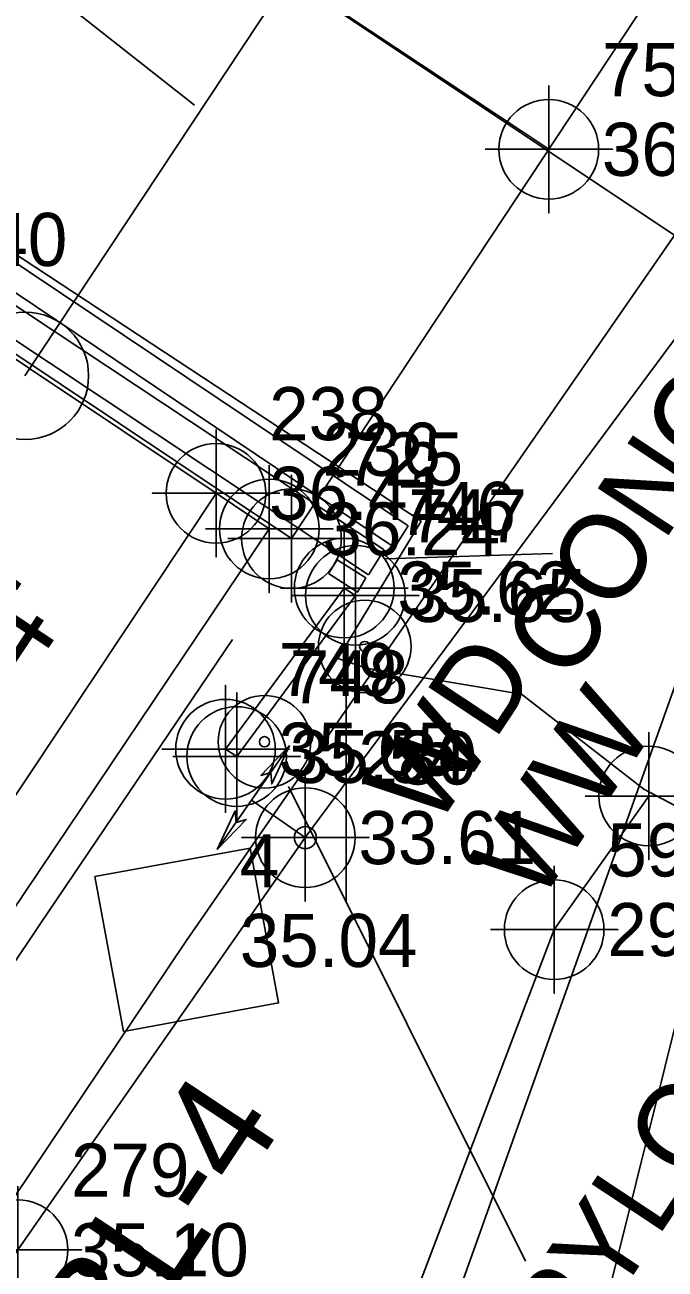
# Model space of a CAD drawing. Extents: x 2603627 to 2605187, y 896619 to 899063.
# Drawn here: x 2604537.3 to 2604567.5, y 898109 to 898167.5 of the extents above; entities that cross this region are included whole.
import ezdxf

# ---------------------------------------------------------------- set-up
doc = ezdxf.new("R2010")
doc.units = 0
for name, color, linetype in [('CTL Supplemental Horizontal and Vertical CELL', 7, 'Continuous'), ('CTL Supplemental Horizontal and Vertical Cogo Elevation', 7, 'Continuous'), ('CTL Supplemental Horizontal and Vertical Cogo Number', 7, 'Continuous'), ('CTL Supplemental Horizontal and Vertical Text', 7, 'Continuous'), ('Exist DTM Drainline Cogo Elevation', 7, 'Continuous'), ('Exist DTM Drainline Cogo Number', 7, 'Continuous'), ('Exist DTM Drainline Cogo Point CELL', 7, 'Continuous'), ('Exist Guardrail', 7, 'Continuous'), ('Exist Horizontal Alignment', 7, 'Continuous'), ('Exist Horizontal Alignment Point', 7, 'Continuous'), ('Exist Horizontal Baseline Alignment', 7, 'Continuous'), ('Exist Hydro Stream or Body of Water', 7, 'Continuous'), ('Exist Other Culture Located Object CELL', 7, 'Continuous'), ('Exist Other Culture Located Object Leader', 7, 'Continuous'), ('Exist Other Culture Located Object Text', 7, 'Continuous'), ('Exist Property Tie Line', 7, 'Continuous'), ('Exist Property Tie Line Leader', 7, 'Continuous'), ('Exist Right of Way Line', 7, 'Continuous'), ('Exist Roads EOP', 7, 'Continuous'), ('Exist Roads EOP Cogo Elevation', 7, 'Continuous'), ('Exist Roads EOP Cogo Number', 7, 'Continuous'), ('Exist Roads EOP Cogo Point CELL', 7, 'Continuous'), ('Exist Roads EOT', 7, 'Continuous'), ('Exist Roads EOT Cogo Elevation', 7, 'Continuous'), ('Exist Roads EOT Cogo Number', 7, 'Continuous'), ('Exist Roads EOT Cogo Point CELL', 7, 'Continuous'), ('Exist Structure Major Bridge Seam', 7, 'Continuous'), ('Exist Structure Major Bridge Seam Cogo Elevation', 7, 'Continuous'), ('Exist Structure Major Bridge Seam Cogo Number', 7, 'Continuous'), ('Exist Structure Major Bridge Seam Cogo Point CELL', 7, 'Continuous'), ('Exist Structure Major Bridge Seat Top Elevation', 7, 'Continuous'), ('Exist Structure Major Bridge Topo', 7, 'Continuous'), ('Exist Structure Major Bridge WW', 7, 'Continuous'), ('Exist Structure Major Bridge WW Cogo Elevation', 7, 'Continuous'), ('Exist Structure Major Bridge WW Cogo Number', 7, 'Continuous'), ('Exist Structure Major Bridge WW Cogo Point CELL', 7, 'Continuous'), ('Exist Structure Major Bridge WW Leader', 7, 'Continuous'), ('Exist Structure Major Bridge WW Text', 7, 'Continuous'), ('Exist Structure Major Deck Tunnel Box Culvert', 7, 'Continuous'), ('Exist Structure Major Deck Tunnel Box Culvert Cogo Number', 7, 'Continuous'), ('Exist Structure Major Deck Tunnel Box Culvert Cogo Point CELL', 7, 'Continuous'), ('Exist Utilities Water Change of Service SUE CELL', 7, 'Continuous'), ('Exist Utilities Water UG Line SUE LOS B', 7, 'Continuous'), ('Exist Utilities Water UG Line SUE LOS B Cogo Elevation', 7, 'Continuous'), ('Exist Utilities Water UG Line SUE LOS B Cogo Number', 7, 'Continuous'), ('Exist Utilities Water UG Line SUE LOS B Cogo Point CELL', 7, 'Continuous'), ('Exist Utilities Water UG Line SUE LOS C', 7, 'Continuous')]:
    doc.layers.add(name, color=color, linetype=linetype)

# ---------------------------------------------------------------- blocks, each defined once
blk = doc.blocks.new('EXIST UTILITIES WATER UG LINE SUE LOS B COGO POINT')
at = {"layer": 'Exist Utilities Water UG Line SUE LOS B Cogo Point CELL'}
blk.add_lwpolyline([(0, 0.06), (0, -0.06), (0, 0), (0.06, 0), (-0.06, 0)], dxfattribs=at)
blk.add_circle((0, 0), 0.0469, dxfattribs=at)
blk = doc.blocks.new('EXIST DTM DRAINLINE COGO POINT')
at = {"layer": 'Exist DTM Drainline Cogo Point CELL'}
blk.add_lwpolyline([(0, 0.06), (0, -0.06), (0, 0), (0.06, 0), (-0.06, 0)], dxfattribs=at)
blk.add_circle((0, 0), 0.0469, dxfattribs=at)
blk = doc.blocks.new('EXIST STRUCTURE MAJOR DECK TUNNEL BOX CULVERT COGO POINT')
at = {"layer": 'Exist Structure Major Deck Tunnel Box Culvert Cogo Point CELL'}
blk.add_lwpolyline([(-0.06, 0), (0.06, 0), (0, 0), (0, 0.06), (0, -0.06)], dxfattribs=at)
blk.add_circle((0, 0), 0.0469, dxfattribs=at)
blk = doc.blocks.new('EXIST BRIDGE SEAM COGO POINT')
at = {"layer": 'Exist Structure Major Bridge Seam Cogo Point CELL'}
blk.add_lwpolyline([(0, 0.06), (0, -0.06), (0, 0), (0.06, 0), (-0.06, 0)], dxfattribs=at)
blk.add_circle((0, 0), 0.0469, dxfattribs=at)
blk = doc.blocks.new('EXIST ROADS EOT COGO POINT')
at = {"layer": 'Exist Roads EOT Cogo Point CELL'}
blk.add_lwpolyline([(0, 0.06), (0, -0.06), (0, 0), (-0.06, 0), (0.06, 0)], dxfattribs=at)
blk.add_circle((0, 0), 0.0469, dxfattribs=at)
blk = doc.blocks.new('EXIST ROADS EOP COGO POINT')
at = {"layer": 'Exist Roads EOP Cogo Point CELL'}
blk.add_lwpolyline([(0, 0.06), (0, -0.06), (0, 0), (0.06, 0), (-0.06, 0)], dxfattribs=at)
blk.add_circle((0, 0), 0.0469, dxfattribs=at)
blk = doc.blocks.new('CTL SUPPLEMENTAL HORIZONTAL AND VERTICAL')
at = {"layer": 'CTL Supplemental Horizontal and Vertical CELL'}
blk.add_line((0, 0), (0, 0), dxfattribs=at)
blk.add_lwpolyline([(-0.1043, 0.0004), (0.0005, 0.1052), (0.1055, 0.0002), (0.0007, -0.1047)], close=True, dxfattribs=at)
blk = doc.blocks.new('EXIST STRUCTURE MAJOR BRIDGE WW COGO POINT')
at = {"layer": 'Exist Structure Major Bridge WW Cogo Point CELL'}
blk.add_lwpolyline([(-0.06, 0), (0.06, 0), (0, 0), (0, 0.06), (0, -0.06)], dxfattribs=at)
blk.add_circle((0, 0), 0.0469, dxfattribs=at)

msp = doc.modelspace()

# ---------------------------------------------------------------- linework, layer by layer
at = {"layer": 'Exist Guardrail'}
msp.add_lwpolyline([(2604547.116, 898138.593), (2604538.083, 898125.227), (2604525.862, 898106.986), (2604516.084, 898089.953)], dxfattribs=at)
at = {"layer": 'Exist Horizontal Alignment'}
msp.add_line((2604537.349, 898151.011), (2604647.762, 898317.915), dxfattribs=at)
at = {"layer": 'Exist Horizontal Alignment Point'}
msp.add_circle((2604537.349, 898151.011), 3, dxfattribs=at)
at = {"layer": 'Exist Horizontal Baseline Alignment'}
for p, q in [((2604544.961, 898124.436), (2604793.601, 898483.903)), ((2604301.74, 897762.526), (2604544.961, 898124.436))]:
    msp.add_line(p, q, dxfattribs=at)
at = {"layer": 'Exist Hydro Stream or Body of Water'}
for p, q in [((2604526.341, 898163.681), (2604553.006, 898146.143)), ((2604562.259, 898124.945), (2604566.71, 898131.232))]:
    msp.add_line(p, q, dxfattribs=at)
for points in [[(2604553.006, 898146.143), (2604556, 898144.174)], [(2604556, 898144.174), (2604552.073, 898137.7)], [(2604552.073, 898137.7), (2604553.43, 898137.243), (2604560.726, 898136.028), (2604566.473, 898131.553)], [(2604566.473, 898131.553), (2604607.177, 898110.112)], [(2604496.633, 897894.568), (2604506.622, 897939.052), (2604520.359, 897991.754), (2604531.2, 898032.054), (2604542.791, 898072.726), (2604553.749, 898102.573), (2604562.259, 898124.945)]]:
    msp.add_lwpolyline(points, dxfattribs=at)
at = {"layer": 'Exist Other Culture Located Object CELL'}
for centre, radius in [((2604553.343, 898138.272), 2.18), ((2604553.343, 898138.272), 0.24), ((2604548.623, 898133.786), 2.18), ((2604548.623, 898133.786), 0.24)]:
    msp.add_circle(centre, radius, dxfattribs=at)
at = {"layer": 'Exist Other Culture Located Object Leader'}
for p, q in [((2604552.474, 898136.112), (2604552.474, 898126.227)), ((2604549.749, 898131.676), (2604560.915, 898109.347))]:
    msp.add_line(p, q, dxfattribs=at)
at = {"layer": 'Exist Property Tie Line'}
for p, q in [((2604598.893, 898244.519), (2604562.447, 898098.35)), ((2604545.339, 898163.743), (2604506.2, 898194.55)), ((2604549.449, 898169.943), (2604591.342, 898142.006))]:
    msp.add_line(p, q, dxfattribs=at)
at = {"layer": 'Exist Property Tie Line Leader'}
msp.add_lwpolyline([(2604573.79, 898143.82), (2604569.62, 898141.109), (2604502.964, 897954.217), (2604488.283, 897929.59)], dxfattribs=at)
at = {"layer": 'Exist Right of Way Line'}
msp.add_arc((2574512.676, 918013.514), 36050, 326.4094331, 326.5137949, dxfattribs=at)
at = {"layer": 'Exist Roads EOP'}
msp.add_line((2604519.702, 898100.467), (2604548.851, 898143.803), dxfattribs=at)
msp.add_lwpolyline([(2604526.478, 898158.766), (2604528.48, 898157.427), (2604537.571, 898151.347), (2604546.345, 898145.48), (2604548.851, 898143.803)], dxfattribs=at)
at = {"layer": 'Exist Roads EOT'}
msp.add_line((2604517.139, 898101.524), (2604546.328, 898145.455), dxfattribs=at)
at = {"layer": 'Exist Structure Major Bridge Seam'}
msp.add_line((2604537.493, 898177.943), (2604562.005, 898161.67), dxfattribs=at)
at = {"layer": 'Exist Structure Major Bridge Topo'}
for p, q in [((2604523.901, 898165.046), (2604555.386, 898143.946)), ((2604554.745, 898142.934), (2604523.25, 898164.094)), ((2604555.386, 898143.946), (2604554.745, 898142.934))]:
    msp.add_line(p, q, dxfattribs=at)
at = {"layer": 'Exist Structure Major Bridge WW'}
for p, q in [((2604523.047, 898163.49), (2604554.258, 898142.816)), ((2604553.519, 898141.638), (2604522.278, 898162.411)), ((2604554.258, 898142.816), (2604553.519, 898141.638)), ((2604546.79, 898133.436), (2604552.378, 898141.018)), ((2604552.378, 898141.018), (2604552.904, 898140.673)), ((2604552.904, 898140.673), (2604547.316, 898133.091)), ((2604546.79, 898133.436), (2604547.316, 898133.091))]:
    msp.add_line(p, q, dxfattribs=at)
msp.add_lwpolyline([(2604551.638, 898141.703), (2604552.041, 898142.349), (2604553.398, 898141.495), (2604552.999, 898140.831), (2604551.638, 898141.703)], dxfattribs=at)
at = {"layer": 'Exist Structure Major Bridge WW Leader'}
msp.add_line((2604554.313, 898142.394), (2604562.188, 898142.645), dxfattribs=at)
at = {"layer": 'Exist Structure Major Deck Tunnel Box Culvert'}
msp.add_lwpolyline([(2604525.453, 898159.692), (2604549.566, 898196.253), (2604574.197, 898180.119), (2604549.896, 898143.345), (2604525.453, 898159.692)], dxfattribs=at)
at = {"layer": 'Exist Utilities Water Change of Service SUE CELL'}
for p, q in [((2604549.81, 898133.611), (2604546.4, 898128.721)), ((2604548.017, 898131.04), (2604549.81, 898133.611)), ((2604550.547, 898129.275), (2604548.017, 898131.04)), ((2604550.547, 898129.275), (2604550.547, 898129.275))]:
    msp.add_line(p, q, dxfattribs=at)
for points in [[(2604549.81, 898133.611), (2604548.965, 898131.798), (2604548.923, 898132.339), (2604548.454, 898132.201)], [(2604546.4, 898128.721), (2604547.245, 898130.534), (2604547.287, 898129.993), (2604547.756, 898130.131)]]:
    msp.add_lwpolyline(points, close=True, dxfattribs=at)
msp.add_circle((2604550.547, 898129.275), 0.517, dxfattribs=at)
at = {"layer": 'Exist Utilities Water UG Line SUE LOS B'}
msp.add_lwpolyline([(2604076.502, 897391.6), (2604089.191, 897412.441), (2604108.022, 897444.81), (2604130.464, 897486.167), (2604138.607, 897502.499), (2604141.743, 897510.424), (2604157.294, 897542.112), (2604195.613, 897598.858), (2604232.991, 897655.201), (2604269.717, 897709.187), (2604303.431, 897758.706), (2604343.238, 897819.021), (2604371.6, 897861.277), (2604402.524, 897906.632), (2604434.42, 897955.25), (2604460.628, 897996.692), (2604477.786, 898022.594), (2604502.249, 898059.637), (2604529.396, 898098.892), (2604530.468, 898100.429), (2604537.018, 898109.876), (2604550.547, 898129.275)], dxfattribs=at)
at = {"layer": 'Exist Utilities Water UG Line SUE LOS C'}
msp.add_line((2604550.547, 898129.275), (2604590.411, 898183.073), dxfattribs=at)

# ---------------------------------------------------------------- block references
at = {"layer": 'CTL Supplemental Horizontal and Vertical CELL', "xscale": 49.99999999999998, "yscale": 49.99999999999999, "rotation": 55.39369554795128}
msp.add_blockref('CTL SUPPLEMENTAL HORIZONTAL AND VERTICAL', (2604544.961, 898124.436), dxfattribs=at)
at = {"layer": 'Exist DTM Drainline Cogo Point CELL', "xscale": 50, "yscale": 50}
for p in [(2604566.71, 898131.232), (2604562.259, 898124.945)]:
    msp.add_blockref('EXIST DTM DRAINLINE COGO POINT', p, dxfattribs=at)
at = {"layer": 'Exist Roads EOP Cogo Point CELL', "xscale": 50, "yscale": 50}
msp.add_blockref('EXIST ROADS EOP COGO POINT', (2604548.851, 898143.803), dxfattribs=at)
at = {"layer": 'Exist Roads EOT Cogo Point CELL', "xscale": 50, "yscale": 50}
msp.add_blockref('EXIST ROADS EOT COGO POINT', (2604546.345, 898145.48), dxfattribs=at)
at = {"layer": 'Exist Structure Major Bridge Seam Cogo Point CELL', "xscale": 50, "yscale": 50}
msp.add_blockref('EXIST BRIDGE SEAM COGO POINT', (2604562.005, 898161.67), dxfattribs=at)
at = {"layer": 'Exist Structure Major Bridge WW Cogo Point CELL', "xscale": 50, "yscale": 50}
for p in [(2604552.378, 898141.018), (2604552.904, 898140.673), (2604546.79, 898133.436), (2604547.316, 898133.091)]:
    msp.add_blockref('EXIST STRUCTURE MAJOR BRIDGE WW COGO POINT', p, dxfattribs=at)
at = {"layer": 'Exist Structure Major Deck Tunnel Box Culvert Cogo Point CELL', "xscale": 50, "yscale": 50}
msp.add_blockref('EXIST STRUCTURE MAJOR DECK TUNNEL BOX CULVERT COGO POINT', (2604549.896, 898143.345), dxfattribs=at)
at = {"layer": 'Exist Utilities Water UG Line SUE LOS B Cogo Point CELL', "xscale": 50, "yscale": 50}
for p in [(2604550.547, 898129.275), (2604537.018, 898109.876)]:
    msp.add_blockref('EXIST UTILITIES WATER UG LINE SUE LOS B COGO POINT', p, dxfattribs=at)

# ---------------------------------------------------------------- texts
at = {"layer": 'CTL Supplemental Horizontal and Vertical Cogo Elevation'}
msp.add_text('35.04', height=2.5, dxfattribs=at).set_placement((2604547.461, 898123.186))
at = {"layer": 'CTL Supplemental Horizontal and Vertical Cogo Number'}
msp.add_text('4', height=2.5, dxfattribs=at).set_placement((2604547.461, 898126.936))
at = {"layer": 'CTL Supplemental Horizontal and Vertical Text'}
msp.add_text('BL-4', height=5, rotation=56.40943, dxfattribs=at).set_placement((2604541.722, 898103.983))
at = {"layer": 'Exist DTM Drainline Cogo Elevation'}
msp.add_text('29.25', height=2.5, dxfattribs=at).set_placement((2604564.759, 898123.695))
at = {"layer": 'Exist DTM Drainline Cogo Number'}
msp.add_text('597', height=2.5, dxfattribs=at).set_placement((2604564.759, 898127.445))
at = {"layer": 'Exist Other Culture Located Object Text'}
msp.add_text('WD PYLONS', height=4, rotation=56.47848, dxfattribs=at).set_placement((2604557.435, 898095.773))
at = {"layer": 'Exist Roads EOP Cogo Elevation'}
msp.add_text('36.24', height=2.5, dxfattribs=at).set_placement((2604551.351, 898142.553))
at = {"layer": 'Exist Roads EOP Cogo Number'}
msp.add_text('236', height=2.5, dxfattribs=at).set_placement((2604551.351, 898146.303))
at = {"layer": 'Exist Roads EOT Cogo Elevation'}
for s, p in [('36.40', (2604530.98, 898156.177)), ('36.41', (2604548.845, 898144.23))]:
    msp.add_text(s, height=2.5, dxfattribs=at).set_placement(p)
at = {"layer": 'Exist Roads EOT Cogo Number'}
msp.add_text('238', height=2.5, dxfattribs=at).set_placement((2604548.845, 898147.98))
at = {"layer": 'Exist Structure Major Bridge Seam Cogo Elevation'}
msp.add_text('36.23', height=2.5, dxfattribs=at).set_placement((2604564.505, 898160.421))
at = {"layer": 'Exist Structure Major Bridge Seam Cogo Number'}
msp.add_text('750', height=2.5, dxfattribs=at).set_placement((2604564.505, 898164.171))
at = {"layer": 'Exist Structure Major Bridge Seat Top Elevation'}
msp.add_text("BRIDGE SEAT=33.04'", height=4, rotation=56.40944, dxfattribs=at).set_placement((2604510.053, 898095.415))
at = {"layer": 'Exist Structure Major Bridge WW Cogo Elevation'}
for s, p in [('35.62', (2604554.878, 898139.768)), ('35.65', (2604555.404, 898139.423)), ('35.65', (2604549.29, 898132.186)), ('35.54', (2604549.817, 898131.841))]:
    msp.add_text(s, height=2.5, dxfattribs=at).set_placement(p)
at = {"layer": 'Exist Structure Major Bridge WW Cogo Number'}
for s, p in [('746', (2604554.878, 898143.518)), ('747', (2604555.404, 898143.173)), ('749', (2604549.29, 898135.936)), ('748', (2604549.817, 898135.591))]:
    msp.add_text(s, height=2.5, dxfattribs=at).set_placement(p)
at = {"layer": 'Exist Structure Major Bridge WW Text'}
for s, p in [('CONC', (2604562.972, 898136.452)), ('WD ', (2604556.645, 898129.57)), ('WW', (2604561.508, 898126.047))]:
    msp.add_text(s, height=4, rotation=56.47848, dxfattribs=at).set_placement(p)
at = {"layer": 'Exist Structure Major Deck Tunnel Box Culvert Cogo Number'}
msp.add_text('725', height=2.5, dxfattribs=at).set_placement((2604552.396, 898145.845))
at = {"layer": 'Exist Utilities Water UG Line SUE LOS B Cogo Elevation'}
for s, p in [('33.61', (2604553.047, 898128.025)), ('35.10', (2604539.518, 898108.626))]:
    msp.add_text(s, height=2.5, dxfattribs=at).set_placement(p)
at = {"layer": 'Exist Utilities Water UG Line SUE LOS B Cogo Number'}
for s, p in [('280', (2604553.047, 898131.775)), ('279', (2604539.518, 898112.376))]:
    msp.add_text(s, height=2.5, dxfattribs=at).set_placement(p)

doc.saveas('drawing.dxf')
